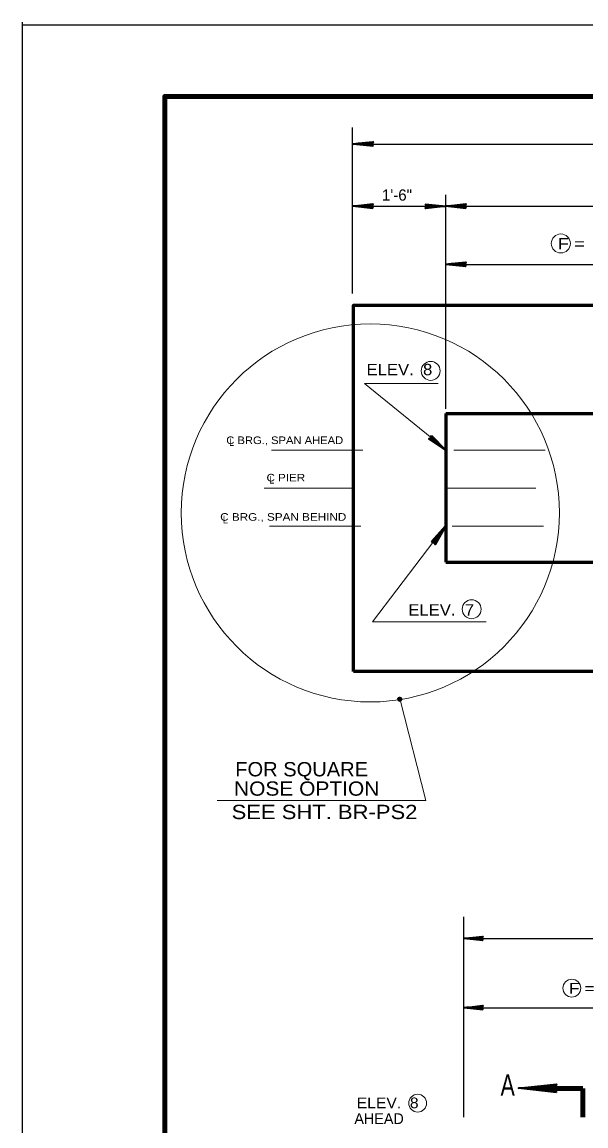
# Model space of a CAD drawing. Extents: x 1.6 to 19.9, y 2.8 to 9.5.
# Drawn here: x 16.267 to 16.884, y 8.339 to 9.549 of the extents above; entities that cross this region are included whole.
import ezdxf

# ---------------------------------------------------------------- set-up
doc = ezdxf.new("R2010")
doc.units = 0
doc.header["$LTSCALE"] = 0.0047
doc.linetypes.add('DOT_DASHED', pattern=[7.7, 5, -1.2, 0.3, -1.2])
doc.layers.add('1', color=7, linetype='Continuous', lineweight=35)
doc.layers.add('5', color=7, linetype='Continuous', lineweight=13)

msp = doc.modelspace()

# ---------------------------------------------------------------- linework, layer by layer
at = {"layer": '1', "lineweight": 25}
for p, q in [((16.26675, 9.5485), (16.26675, 7.2855)), ((19.894917, 9.545083), (16.26675, 9.545083)), ((16.62875, 9.251083), (16.62875, 9.433167)), ((16.629583, 9.414833), (17.4315, 9.414833)), ((16.730833, 9.32475), (16.730833, 9.359083)), ((16.633583, 9.34675), (17.42725, 9.34675)), ((16.730833, 9.236333), (16.730833, 9.339083)), ((16.730833, 9.125), (16.730833, 9.283083)), ((16.730833, 9.283083), (17.332167, 9.283083)), ((16.75075, 8.349), (16.75075, 8.56825)), ((16.75075, 8.46875), (17.3195, 8.46875))]:
    msp.add_line(p, q, dxfattribs=at)
at = {"layer": '1'}
for p, q in [((16.651167, 9.414917), (16.62925, 9.414917)), ((16.650667, 9.412833), (16.63425, 9.414667)), ((16.650667, 9.412833), (16.63425, 9.414667)), ((16.650667, 9.413), (16.63425, 9.414667)), ((16.65075, 9.413333), (16.634333, 9.415)), ((16.650667, 9.413083), (16.634333, 9.414833)), ((16.650667, 9.417083), (16.63525, 9.415333)), ((16.650667, 9.416833), (16.63525, 9.415167)), ((16.65075, 9.416667), (16.635417, 9.414917)), ((16.65075, 9.416333), (16.635417, 9.414667)), ((16.6505, 9.348833), (16.635167, 9.347167)), ((16.6505, 9.348667), (16.635167, 9.347)), ((16.650583, 9.348333), (16.63525, 9.34675)), ((16.650583, 9.348083), (16.63525, 9.3465)), ((16.708833, 9.348833), (16.725417, 9.347)), ((16.708833, 9.34875), (16.725417, 9.347)), ((16.708833, 9.348667), (16.725417, 9.346833)), ((16.708833, 9.348333), (16.725417, 9.346667)), ((16.708833, 9.3455), (16.724167, 9.347)), ((16.708917, 9.348917), (16.725417, 9.347083)), ((16.752333, 9.348833), (16.737083, 9.347167)), ((16.752333, 9.348667), (16.737083, 9.347)), ((16.752417, 9.348333), (16.737167, 9.34675)), ((16.752417, 9.348083), (16.737167, 9.3465)), ((16.651, 9.34675), (16.629, 9.34675)), ((16.6505, 9.344583), (16.634167, 9.3465)), ((16.6505, 9.344667), (16.634167, 9.3465)), ((16.6505, 9.34475), (16.634167, 9.3465)), ((16.650583, 9.345167), (16.63425, 9.346833)), ((16.6505, 9.344917), (16.63425, 9.34675)), ((16.7085, 9.34675), (16.730583, 9.34675)), ((16.708833, 9.345167), (16.724167, 9.34675)), ((16.708833, 9.344917), (16.724167, 9.3465)), ((16.708917, 9.344583), (16.724167, 9.346417)), ((16.752833, 9.34675), (16.730833, 9.34675)), ((16.752333, 9.344583), (16.736083, 9.3465)), ((16.752333, 9.344667), (16.736083, 9.3465)), ((16.752333, 9.34475), (16.736083, 9.3465)), ((16.752417, 9.345167), (16.736167, 9.346833)), ((16.752333, 9.344917), (16.736167, 9.34675)), ((16.753, 9.283083), (16.730917, 9.283083)), ((16.7525, 9.281), (16.736083, 9.282833)), ((16.7525, 9.281083), (16.736083, 9.282833)), ((16.7525, 9.280917), (16.736083, 9.28275)), ((16.752583, 9.281417), (16.736167, 9.283167)), ((16.7525, 9.281167), (16.736167, 9.283)), ((16.7525, 9.285167), (16.737167, 9.2835)), ((16.7525, 9.285), (16.737167, 9.283333)), ((16.752583, 9.28475), (16.73725, 9.283083)), ((16.752583, 9.2845), (16.73725, 9.282833)), ((16.71375, 9.093833), (16.73075, 9.079583)), ((16.715167, 9.095), (16.72675, 9.083083)), ((16.715167, 9.094833), (16.726583, 9.083)), ((16.71525, 9.095083), (16.726833, 9.083083)), ((16.715417, 9.09525), (16.726833, 9.083333)), ((16.715417, 9.09525), (16.726833, 9.08325)), ((16.712833, 9.092), (16.725583, 9.0835)), ((16.712917, 9.092083), (16.72575, 9.083583)), ((16.713, 9.092333), (16.725833, 9.083667)), ((16.713083, 9.092583), (16.726083, 9.083917)), ((16.71775, 8.978417), (16.7305, 8.9965)), ((16.71575, 8.979167), (16.726583, 8.991583)), ((16.71575, 8.979083), (16.726667, 8.991583)), ((16.71575, 8.979), (16.726833, 8.9915)), ((16.715833, 8.979), (16.726833, 8.991417)), ((16.716083, 8.97875), (16.727, 8.99125)), ((16.71625, 8.98), (16.72725, 8.9925)), ((16.71625, 8.980083), (16.727083, 8.992417)), ((16.71625, 8.979833), (16.727417, 8.992417)), ((16.716417, 8.979833), (16.727417, 8.99225)), ((16.716583, 8.97975), (16.7275, 8.992083)), ((16.71725, 8.977417), (16.730083, 8.99575)), ((16.718667, 8.977083), (16.726083, 8.990583)), ((16.718833, 8.977), (16.72625, 8.990417)), ((16.719083, 8.976833), (16.7265, 8.990417)), ((16.719167, 8.97775), (16.726583, 8.9915)), ((16.719167, 8.976667), (16.726583, 8.990333)), ((16.71925, 8.97775), (16.72675, 8.991333)), ((16.7195, 8.977667), (16.727, 8.991167)), ((16.719667, 8.9775), (16.727083, 8.991)), ((16.771417, 8.544667), (16.75075, 8.544667)), ((16.771, 8.542667), (16.755583, 8.544417)), ((16.771, 8.54275), (16.755583, 8.544417)), ((16.771, 8.542583), (16.755583, 8.544333)), ((16.771083, 8.543083), (16.755667, 8.54475)), ((16.771, 8.542833), (16.755667, 8.5445)), ((16.771, 8.546583), (16.756667, 8.545)), ((16.771, 8.546417), (16.756667, 8.544833)), ((16.771083, 8.54625), (16.756667, 8.544667)), ((16.771083, 8.546), (16.756667, 8.544417)), ((16.7715, 8.46875), (16.750833, 8.46875)), ((16.771083, 8.46675), (16.755667, 8.4685)), ((16.771083, 8.466833), (16.755667, 8.4685)), ((16.771083, 8.466917), (16.755667, 8.4685)), ((16.771167, 8.46725), (16.75575, 8.468833)), ((16.771083, 8.467), (16.75575, 8.46875)), ((16.771083, 8.47075), (16.756667, 8.469167)), ((16.771083, 8.470583), (16.756667, 8.469)), ((16.771167, 8.470333), (16.75675, 8.46875)), ((16.771167, 8.470083), (16.75675, 8.4685)), ((16.852083, 8.380583), (16.810667, 8.380583)), ((16.851167, 8.376833), (16.820417, 8.380083)), ((16.851167, 8.376667), (16.820417, 8.38)), ((16.851167, 8.3765), (16.820417, 8.379833)), ((16.851333, 8.377333), (16.8205, 8.38075)), ((16.851167, 8.377), (16.8205, 8.380417)), ((16.851167, 8.3845), (16.822417, 8.381333)), ((16.851167, 8.384083), (16.822417, 8.381)), ((16.851333, 8.383583), (16.822667, 8.3805)), ((16.851417, 8.383167), (16.822667, 8.38))]:
    msp.add_line(p, q, dxfattribs=at)
at = {"layer": '1', "lineweight": 13}
for p, q in [((16.642, 9.1525), (16.722667, 9.1525)), ((16.642, 9.1525), (16.727083, 9.083333)), ((16.650667, 8.8915), (16.7305, 8.9965)), ((16.650667, 8.8915), (16.775, 8.8915)), ((16.709, 8.695667), (16.68075, 8.80625)), ((16.4805, 8.695667), (16.709, 8.695667))]:
    msp.add_line(p, q, dxfattribs=at)
at = {"layer": '1', "lineweight": 60}
for p, q in [((16.731, 9.119583), (16.731, 8.957)), ((16.731, 9.119583), (17.252, 9.119583)), ((16.731, 8.957), (17.25775, 8.957)), ((17.43225, 8.837167), (16.629667, 8.837167))]:
    msp.add_line(p, q, dxfattribs=at)
at = {"layer": '1', "linetype": 'DOT_DASHED', "lineweight": 13}
for p, q in [((16.539833, 9.079667), (17.478917, 9.079667)), ((17.0295, 9.038), (16.532083, 9.038)), ((16.537917, 8.996417), (17.4745, 8.996417))]:
    msp.add_line(p, q, dxfattribs=at)
at = {"layer": '1', "lineweight": 40}
for p, q in [((16.679, 8.806083), (16.6815, 8.805667)), ((16.67925, 8.807667), (16.679083, 8.806)), ((16.679083, 8.807167), (16.681667, 8.80675)), ((16.679083, 8.807083), (16.681667, 8.806583)), ((16.679083, 8.806917), (16.681583, 8.806417)), ((16.679083, 8.806833), (16.681583, 8.806333)), ((16.679083, 8.806583), (16.681583, 8.806083)), ((16.679083, 8.806333), (16.681583, 8.806)), ((16.679083, 8.80625), (16.6815, 8.805833)), ((16.679083, 8.806083), (16.6815, 8.80575)), ((16.679333, 8.807667), (16.67925, 8.806)), ((16.67925, 8.807667), (16.68175, 8.807333)), ((16.67925, 8.807583), (16.68175, 8.807083)), ((16.67925, 8.807583), (16.68175, 8.80725)), ((16.67925, 8.8075), (16.68175, 8.806917)), ((16.67925, 8.80725), (16.681667, 8.806833)), ((16.679333, 8.807917), (16.68175, 8.807583)), ((16.679417, 8.807667), (16.679333, 8.806)), ((16.679667, 8.807667), (16.679417, 8.806)), ((16.679667, 8.807667), (16.679667, 8.806)), ((16.679917, 8.807667), (16.679833, 8.806)), ((16.68, 8.807667), (16.679917, 8.806)), ((16.680083, 8.807667), (16.68, 8.806)), ((16.68025, 8.807667), (16.680083, 8.806)), ((16.680333, 8.807667), (16.68025, 8.806)), ((16.680417, 8.807667), (16.680333, 8.806)), ((16.680667, 8.807667), (16.680417, 8.806)), ((16.68075, 8.807583), (16.680667, 8.805833)), ((16.681, 8.807583), (16.68075, 8.805833)), ((16.681083, 8.807583), (16.681, 8.805833)), ((16.681083, 8.807583), (16.681, 8.805833)), ((16.681167, 8.807583), (16.681083, 8.805833)), ((16.68125, 8.807583), (16.681167, 8.805833)), ((16.681417, 8.807583), (16.68125, 8.805833)), ((16.6815, 8.807583), (16.681417, 8.805833)), ((16.681583, 8.807583), (16.6815, 8.805833)), ((16.681667, 8.807583), (16.681583, 8.805833)), ((16.681917, 8.807583), (16.68175, 8.805833))]:
    msp.add_line(p, q, dxfattribs=at)
at = {"layer": '1', "lineweight": 90}
for q in [(16.850417, 8.380417), (16.881, 8.349083)]:
    msp.add_line((16.881, 8.380417), q, dxfattribs=at)
at = {"layer": '1', "lineweight": 106}
msp.add_lwpolyline([(19.823, 7.367), (19.823, 9.467), (16.423, 9.467), (16.423, 7.367)], dxfattribs=at)
at = {"layer": '1'}
for points in [[(16.651167, 9.412583), (16.62925, 9.414917), (16.651167, 9.417417), (16.65, 9.414917)], [(16.651, 9.344333), (16.629, 9.34675), (16.651, 9.349333), (16.649917, 9.34675)], [(16.7085, 9.349083), (16.730583, 9.34675), (16.7085, 9.344333), (16.709583, 9.34675)], [(16.752833, 9.344333), (16.730833, 9.34675), (16.752833, 9.349333), (16.75175, 9.34675)], [(16.753, 9.280667), (16.730917, 9.283083), (16.753, 9.285583), (16.751833, 9.283083)], [(16.71525, 9.09575), (16.73075, 9.079583), (16.712167, 9.092), (16.714583, 9.093083)], [(16.715667, 8.979833), (16.7305, 8.9965), (16.71975, 8.977), (16.718333, 8.979333)], [(16.715167, 8.978833), (16.730083, 8.99575), (16.71925, 8.976083), (16.717833, 8.9785)], [(16.771417, 8.542333), (16.75075, 8.544667), (16.771417, 8.547), (16.770417, 8.544667)], [(16.7715, 8.4665), (16.750833, 8.46875), (16.7715, 8.471083), (16.770417, 8.46875)], [(16.852083, 8.376), (16.810667, 8.380583), (16.852083, 8.385167), (16.849917, 8.3805)]]:
    msp.add_lwpolyline(points, close=True, dxfattribs=at)
for points in [[(16.64975, 9.414667), (16.63975, 9.4145), (16.63975, 9.41475), (16.641833, 9.414667), (16.64975, 9.4145), (16.64325, 9.414417), (16.65, 9.414083), (16.645333, 9.414), (16.650167, 9.41375), (16.642583, 9.414417), (16.632917, 9.41475), (16.63475, 9.415333), (16.63225, 9.415083), (16.64975, 9.415167), (16.644417, 9.415417), (16.65, 9.415417), (16.638667, 9.414667), (16.65, 9.415917), (16.649583, 9.414667), (16.6505, 9.413167), (16.65, 9.4135), (16.649583, 9.414417), (16.648917, 9.414083), (16.649417, 9.413417), (16.649833, 9.415), (16.65025, 9.415917), (16.650667, 9.417083)], [(16.6495, 9.3465), (16.639583, 9.346417), (16.639583, 9.346667), (16.641667, 9.3465), (16.6495, 9.346417), (16.643167, 9.34625), (16.649833, 9.346083), (16.64525, 9.345917), (16.65, 9.34575), (16.6425, 9.34625), (16.63275, 9.346667), (16.634583, 9.347167), (16.632083, 9.347), (16.6495, 9.347), (16.64425, 9.347333), (16.649833, 9.347333), (16.6385, 9.3465), (16.649917, 9.34775), (16.649417, 9.3465), (16.650333, 9.345083), (16.649917, 9.3455), (16.649417, 9.34625), (16.64875, 9.346), (16.649167, 9.345417), (16.649583, 9.346833), (16.65, 9.34775), (16.6505, 9.348833)], [(16.709833, 9.347), (16.71975, 9.347167), (16.719667, 9.347), (16.717833, 9.347), (16.709833, 9.347167), (16.71625, 9.347333), (16.709583, 9.3475), (16.714167, 9.347667), (16.709417, 9.347917), (16.717083, 9.347333), (16.726833, 9.347), (16.724833, 9.346417), (16.727583, 9.346667), (16.709833, 9.3465), (16.715083, 9.34625), (16.709583, 9.34625), (16.720833, 9.347), (16.7095, 9.345833), (16.71, 9.347), (16.709, 9.3485), (16.7095, 9.348083), (16.71, 9.347333), (16.7105, 9.347583), (16.710167, 9.34825), (16.70975, 9.34675), (16.709333, 9.345833), (16.708917, 9.344667)], [(16.751417, 9.3465), (16.741583, 9.346417), (16.741583, 9.346667), (16.7435, 9.3465), (16.751417, 9.346417), (16.745083, 9.34625), (16.751667, 9.346083), (16.747083, 9.345917), (16.751833, 9.34575), (16.744333, 9.34625), (16.734583, 9.346667), (16.7365, 9.347167), (16.733917, 9.347), (16.751417, 9.347), (16.746167, 9.347333), (16.751667, 9.347333), (16.740417, 9.3465), (16.75175, 9.34775), (16.751333, 9.3465), (16.75225, 9.345083), (16.75175, 9.3455), (16.751333, 9.34625), (16.750667, 9.346), (16.751083, 9.345417), (16.7515, 9.346833), (16.751917, 9.34775), (16.752333, 9.348833)], [(16.7515, 9.282833), (16.741667, 9.282667), (16.741667, 9.282917), (16.743583, 9.282833), (16.7515, 9.282667), (16.745167, 9.2825), (16.75175, 9.282333), (16.747083, 9.282167), (16.751917, 9.281917), (16.744417, 9.2825), (16.734583, 9.282917), (16.736583, 9.2835), (16.733917, 9.28325), (16.7515, 9.283333), (16.746333, 9.283667), (16.75175, 9.283667), (16.7405, 9.282833), (16.751833, 9.284083), (16.751417, 9.282833), (16.752333, 9.281333), (16.751833, 9.281667), (16.751417, 9.2825), (16.750833, 9.28225), (16.75125, 9.281583), (16.751583, 9.283167), (16.752, 9.284083), (16.7525, 9.285167)], [(16.714917, 9.093083), (16.72275, 9.086917), (16.7225, 9.086667), (16.721167, 9.088083), (16.715167, 9.093167), (16.720167, 9.08925), (16.715167, 9.093583), (16.718833, 9.09075), (16.715167, 9.094083), (16.72075, 9.088833), (16.727917, 9.08225), (16.726083, 9.083083), (16.728167, 9.081333), (16.71475, 9.09275), (16.718417, 9.089083), (16.714333, 9.092583), (16.723417, 9.085917), (16.713833, 9.092417), (16.715083, 9.092917), (16.71525, 9.09475), (16.715417, 9.094167), (16.71525, 9.09325), (16.71575, 9.093083), (16.716, 9.093833), (16.71475, 9.092917), (16.713833, 9.0925), (16.712833, 9.091917)], [(16.717833, 8.978833), (16.723417, 8.987083), (16.723583, 8.986833), (16.722333, 8.985417), (16.71775, 8.979), (16.72125, 8.984333), (16.717333, 8.979), (16.719833, 8.982833), (16.716833, 8.979), (16.72175, 8.984917), (16.727583, 8.99275), (16.726833, 8.990667), (16.728333, 8.993083), (16.71825, 8.978667), (16.7215, 8.982667), (16.718333, 8.978333), (16.724167, 8.98775), (16.718667, 8.977833), (16.717917, 8.978833), (16.716167, 8.979), (16.716583, 8.97925), (16.717583, 8.979167), (16.71775, 8.97975), (16.716917, 8.97975), (16.718083, 8.9785), (16.718583, 8.97775), (16.719167, 8.97675)], [(16.718333, 8.979833), (16.723917, 8.988), (16.724083, 8.98775), (16.722917, 8.98625), (16.71825, 8.98), (16.72175, 8.985083), (16.717833, 8.979833), (16.720417, 8.983667), (16.717333, 8.979833), (16.722167, 8.985833), (16.728167, 8.993583), (16.7275, 8.991667), (16.728833, 8.993917), (16.718833, 8.979417), (16.721917, 8.9835), (16.718917, 8.979), (16.72475, 8.98875), (16.719167, 8.978667), (16.718583, 8.979833), (16.716583, 8.979833), (16.71725, 8.980083), (16.718083, 8.980083), (16.718167, 8.980583), (16.7175, 8.980583), (16.718583, 8.979417), (16.719083, 8.9785), (16.719667, 8.977667)], [(16.770083, 8.544417), (16.760833, 8.54425), (16.760833, 8.5445), (16.762667, 8.544417), (16.770083, 8.54425), (16.764167, 8.544083), (16.77025, 8.543917), (16.765917, 8.54375), (16.770417, 8.5435), (16.763417, 8.544083), (16.754167, 8.5445), (16.756083, 8.545), (16.753583, 8.54475), (16.770083, 8.544833), (16.765167, 8.545167), (16.77025, 8.545167), (16.75975, 8.544417), (16.770417, 8.545583), (16.769917, 8.544417), (16.770833, 8.543), (16.770417, 8.54325), (16.769917, 8.544083), (16.769417, 8.543833), (16.769833, 8.54325), (16.770167, 8.54475), (16.7705, 8.545583), (16.771, 8.546583)], [(16.770167, 8.4685), (16.760917, 8.468417), (16.760917, 8.468583), (16.762667, 8.4685), (16.770167, 8.468417), (16.764167, 8.46825), (16.770417, 8.468083), (16.766, 8.467917), (16.7705, 8.467667), (16.7635, 8.46825), (16.75425, 8.468583), (16.756167, 8.469167), (16.753667, 8.468917), (16.770167, 8.469), (16.76525, 8.469333), (16.770417, 8.469333), (16.759833, 8.4685), (16.770417, 8.46975), (16.770083, 8.4685), (16.770917, 8.467167), (16.770417, 8.4675), (16.770083, 8.46825), (16.7695, 8.468), (16.769917, 8.467333), (16.770167, 8.468833), (16.770583, 8.46975), (16.771083, 8.47075)], [(16.84925, 8.38), (16.830833, 8.37975), (16.830917, 8.38025), (16.8345, 8.38), (16.84925, 8.37975), (16.837417, 8.379417), (16.849833, 8.379167), (16.841083, 8.378833), (16.850167, 8.378417), (16.836, 8.3795), (16.817583, 8.38025), (16.821417, 8.38125), (16.816333, 8.38075), (16.84925, 8.381), (16.839667, 8.381583), (16.849833, 8.381583), (16.828667, 8.380083), (16.849917, 8.3825), (16.849167, 8.380083), (16.850917, 8.37725), (16.849917, 8.377833), (16.849167, 8.3795), (16.848083, 8.379), (16.848833, 8.377667), (16.849417, 8.380667), (16.85025, 8.3825), (16.851167, 8.3845)]]:
    msp.add_lwpolyline(points, dxfattribs=at)
at = {"layer": '1', "lineweight": 60}
msp.add_lwpolyline([(16.629667, 8.837167), (16.629667, 9.2385), (17.43225, 9.2385)], dxfattribs=at)
at = {"layer": '1', "lineweight": 40}
msp.add_lwpolyline([(16.67875, 8.80675), (16.682, 8.807167), (16.679083, 8.807667), (16.682, 8.806417), (16.679, 8.806), (16.6815, 8.805583), (16.6815, 8.808), (16.680333, 8.805333), (16.68075, 8.808333), (16.679333, 8.805583), (16.679833, 8.808333), (16.680833, 8.805333), (16.678833, 8.807333), (16.681917, 8.807583), (16.679833, 8.805333), (16.681167, 8.80825), (16.679083, 8.807667), (16.679, 8.806), (16.680333, 8.805333), (16.6815, 8.805583), (16.682, 8.806417), (16.681917, 8.807583), (16.681167, 8.80825), (16.680333, 8.806917), (16.68175, 8.805833), (16.679333, 8.805583), (16.680333, 8.806917), (16.679, 8.807583), (16.68025, 8.808333), (16.680333, 8.807083), (16.681417, 8.805583), (16.678833, 8.807083), (16.680667, 8.8075), (16.6815, 8.808)], dxfattribs=at)
at = {"layer": '1', "lineweight": 25}
msp.add_lwpolyline([(16.75075, 8.54475), (17.049167, 8.54475), (17.317583, 8.54475)], dxfattribs=at)
at = {"layer": '1', "lineweight": 13}
for centre, radius in [((16.856875, 9.305979), 0.010417), ((16.648216, 9.010857), 0.207058), ((16.714334, 9.166369), 0.010363), ((16.759187, 8.905295), 0.010363), ((16.868898, 8.49022), 0.009766), ((16.70007, 8.364283), 0.009766)]:
    msp.add_circle(centre, radius, dxfattribs=at)
at = {"layer": '1', "lineweight": 40}
msp.add_circle((16.680404, 8.806781), 0.001641, dxfattribs=at)

# ---------------------------------------------------------------- texts
at = {"layer": '1'}
msp.add_text('1\'-6"', height=0.01233, dxfattribs=at).set_placement((16.661, 9.352917))
for s, height, width, p in [('C BRG., SPAN AHEAD', 0.008333, 1.1, (16.490417, 9.08625)), ('L', 0.008333, 0.85, (16.493667, 9.084167)), ('C PIER', 0.008249, 1.15, (16.5345, 9.045333)), ('L', 0.00825, 0.9, (16.537333, 9.042917)), ('C BRG., SPAN BEHIND', 0.008333, 1.15, (16.48375, 9.00225)), ('L', 0.008249, 0.9, (16.486583, 8.999417)), ('A', 0.02342, 0.75, (16.790833, 8.372333))]:
    msp.add_text(s, height=height, dxfattribs=dict(at, width=width)).set_placement(p)
at = {"layer": '5'}
for s, height, width, p in [('F =      ', 0.0125, 1.2, (16.853667, 9.2995)), ('ELEV.  8', 0.01242, 1.1, (16.644, 9.161667)), ('ELEV.  7', 0.01242, 1.1, (16.68975, 8.898417)), ('FOR SQUARE', 0.01567, 1.05, (16.50025, 8.72225)), ('NOSE OPTION', 0.01558, 1.1, (16.498917, 8.701083)), ('SEE SHT. BR-PS2', 0.01567, 1.15, (16.49625, 8.675417)), ('F =      ', 0.01175, 1.2, (16.865917, 8.484167)), ('ELEV.  8', 0.01167, 1.1, (16.633333, 8.35875))]:
    msp.add_text(s, height=height, dxfattribs=dict(at, width=width)).set_placement(p)
msp.add_text('AHEAD', height=0.01175, dxfattribs=at).set_placement((16.63075, 8.341417))

doc.saveas('drawing.dxf')
